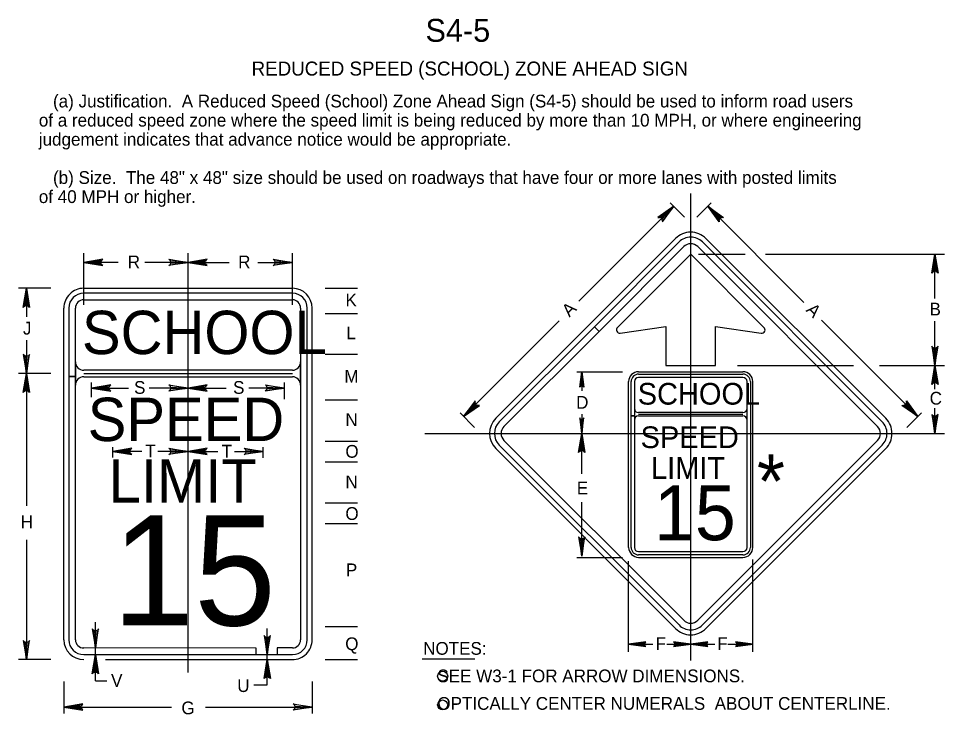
# Model space of a CAD drawing. Extents: x 0.012 to 0.205, y 0.005 to 0.259.
# Drawn here: x 0.023 to 0.2047, y 0.1227 to 0.2592 of the extents above; entities that cross this region are included whole.
import ezdxf

# ---------------------------------------------------------------- set-up
doc = ezdxf.new("R2010")
doc.units = 0
for name, color, linetype in [('1', 7, 'Continuous'), ('2', 7, 'Continuous'), ('3', 7, 'Continuous')]:
    doc.layers.add(name, color=color, linetype=linetype)

# ---------------------------------------------------------------- blocks, each defined once
blk = doc.blocks.new('RARROW')
at = {"layer": '3'}
for p, q in [((-2.156, 0.28500000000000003), (-2.2665, 0.384625)), ((-2.2665, 0.384625), (0, 0)), ((0, 0), (-2.2665, -0.379125)), ((-2.156, 0.28500000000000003), (-2.075625, 0.12075)), ((0, 0), (-2.156, 0.28500000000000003)), ((-2.14975, -0.2705), (0, 0)), ((-2.075625, 0.12075), (0, 0)), ((0, 0), (-2.074, -0.108)), ((-2.2665, -0.379125), (-2.14975, -0.2705)), ((-2.074, -0.108), (-2.14975, -0.2705))]:
    blk.add_line(p, q, dxfattribs=at)

msp = doc.modelspace()

# ---------------------------------------------------------------- linework, layer by layer
at = {"layer": '1'}
for p, q in [((0.15493652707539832, 0.13328541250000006), (0.15493652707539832, 0.22487989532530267)), ((0.1516063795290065, 0.22236153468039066), (0.13298510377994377, 0.203740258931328)), ((0.15373535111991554, 0.2202325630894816), (0.15091590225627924, 0.22305201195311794)), ((0.1561377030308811, 0.2202325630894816), (0.15895715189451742, 0.22305201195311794)), ((0.15826667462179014, 0.22236153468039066), (0.17713821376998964, 0.20348999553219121)), ((0.11667639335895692, 0.18077125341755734), (0.15195819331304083, 0.21605305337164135)), ((0.13602037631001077, 0.19874062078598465), (0.15264550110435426, 0.215365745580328)), ((0.15356191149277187, 0.21444933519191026), (0.1369367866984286, 0.19782421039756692)), ((0.1915929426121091, 0.17916753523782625), (0.15631114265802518, 0.21444933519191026)), ((0.157227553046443, 0.215365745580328), (0.19250935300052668, 0.18008394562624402)), ((0.1931966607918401, 0.18077125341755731), (0.15791486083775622, 0.21605305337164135)), ((0.03580431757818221, 0.20304977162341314), (0.03580431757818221, 0.21317677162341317)), ((0.056281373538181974, 0.20937914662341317), (0.056281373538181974, 0.21317677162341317)), ((0.05628137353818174, 0.13088051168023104), (0.056281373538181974, 0.21283153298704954)), ((0.0767584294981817, 0.20304977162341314), (0.0767584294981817, 0.21317677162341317)), ((0.15493652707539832, 0.2129793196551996), (0.14055945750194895, 0.19860225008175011)), ((0.16931359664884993, 0.19860225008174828), (0.15493652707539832, 0.2129793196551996)), ((0.15645266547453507, 0.2129793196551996), (0.16560148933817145, 0.21297931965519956)), ((0.16962927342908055, 0.21297931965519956), (0.20473300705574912, 0.2129793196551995)), ((0.20285847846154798, 0.20426678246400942), (0.20285847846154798, 0.2129793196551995)), ((0.042595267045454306, 0.21133549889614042), (0.03580431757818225, 0.21133549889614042)), ((0.05628137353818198, 0.21133549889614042), (0.047773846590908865, 0.21133549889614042)), ((0.05628137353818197, 0.21133549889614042), (0.06434530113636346, 0.21133549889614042)), ((0.06998419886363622, 0.21133549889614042), (0.0767584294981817, 0.21133549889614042)), ((0.029344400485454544, 0.20627697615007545), (0.02301502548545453, 0.20627697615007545)), ((0.024563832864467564, 0.20627697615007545), (0.024563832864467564, 0.20068718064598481)), ((0.03580431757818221, 0.20627697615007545), (0.0767584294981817, 0.20627697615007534)), ((0.08321834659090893, 0.20627697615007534), (0.08954772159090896, 0.20627697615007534)), ((0.0767584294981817, 0.2053049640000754), (0.03580431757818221, 0.20530496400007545)), ((0.03580431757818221, 0.20400894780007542), (0.0767584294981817, 0.2040089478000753)), ((0.03191626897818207, 0.13732891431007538), (0.03191626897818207, 0.20238892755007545)), ((0.03288828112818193, 0.20238892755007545), (0.03288828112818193, 0.18894456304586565)), ((0.034184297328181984, 0.18894456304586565), (0.034184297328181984, 0.20238892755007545)), ((0.07837844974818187, 0.20238892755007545), (0.07837844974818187, 0.13732891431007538)), ((0.07967446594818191, 0.13732891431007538), (0.07967446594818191, 0.20238892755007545)), ((0.08064647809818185, 0.13732891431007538), (0.08064647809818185, 0.20238892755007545)), ((0.08321834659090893, 0.20135211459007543), (0.08954772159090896, 0.20135211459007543)), ((0.18059060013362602, 0.20003760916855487), (0.1995051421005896, 0.18112306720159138)), ((0.12912993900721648, 0.1998850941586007), (0.11036791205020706, 0.18112306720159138)), ((0.11736370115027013, 0.18008394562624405), (0.13602037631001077, 0.19874062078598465)), ((0.13602037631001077, 0.19874062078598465), (0.1369367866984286, 0.19782421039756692)), ((0.1369367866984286, 0.19782421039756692), (0.13602037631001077, 0.19874062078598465)), ((0.14109770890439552, 0.19749001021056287), (0.15007652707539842, 0.19879471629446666)), ((0.15007652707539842, 0.19879471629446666), (0.15007652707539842, 0.19114171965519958)), ((0.1597965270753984, 0.19114171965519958), (0.1597965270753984, 0.19879471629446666)), ((0.1597965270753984, 0.19879471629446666), (0.16877534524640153, 0.19749001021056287)), ((0.20285847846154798, 0.19114171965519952), (0.20285847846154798, 0.1998362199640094)), ((0.1369367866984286, 0.19782421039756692), (0.11828011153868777, 0.1791675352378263)), ((0.024563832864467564, 0.19609190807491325), (0.024563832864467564, 0.18956005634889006)), ((0.08321834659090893, 0.19331681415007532), (0.08954772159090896, 0.19331681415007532)), ((0.034184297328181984, 0.19182639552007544), (0.034184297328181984, 0.18729033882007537)), ((0.07837844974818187, 0.18729033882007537), (0.07837844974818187, 0.19182639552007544)), ((0.15007652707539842, 0.19114171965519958), (0.1597965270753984, 0.19114171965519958)), ((0.1641054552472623, 0.19114171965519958), (0.1868912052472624, 0.19114171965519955)), ((0.1919547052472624, 0.19114171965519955), (0.20473300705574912, 0.19114171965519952)), ((0.20285847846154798, 0.18648699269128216), (0.20285847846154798, 0.19114171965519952)), ((0.029344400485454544, 0.18956005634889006), (0.02301502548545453, 0.18956005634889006)), ((0.024563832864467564, 0.18956005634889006), (0.024563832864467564, 0.1635639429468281)), ((0.0767584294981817, 0.19020637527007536), (0.03580431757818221, 0.19020637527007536)), ((0.03580431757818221, 0.1895583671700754), (0.0767584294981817, 0.18955836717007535)), ((0.13257365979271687, 0.18991051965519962), (0.14154986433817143, 0.18991051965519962)), ((0.13355183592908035, 0.18991051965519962), (0.13355183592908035, 0.18614175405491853)), ((0.14469812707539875, 0.18991051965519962), (0.1651749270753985, 0.1899105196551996)), ((0.14469812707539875, 0.18942451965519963), (0.1651749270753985, 0.1894245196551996)), ((0.03288828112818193, 0.18894456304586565), (0.034184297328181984, 0.18894456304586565)), ((0.03288828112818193, 0.18894456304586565), (0.034184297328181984, 0.18894456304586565)), ((0.034184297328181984, 0.18894456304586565), (0.03288828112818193, 0.18894456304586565)), ((0.03288828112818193, 0.18894456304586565), (0.034184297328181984, 0.18894456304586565)), ((0.034184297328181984, 0.18894456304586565), (0.03288828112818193, 0.18894456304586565)), ((0.034184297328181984, 0.18894456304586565), (0.03288828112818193, 0.18894456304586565)), ((0.03288828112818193, 0.18894456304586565), (0.03288828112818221, 0.13732891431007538)), ((0.034184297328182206, 0.13732891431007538), (0.034184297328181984, 0.18894456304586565)), ((0.03580431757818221, 0.18891035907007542), (0.0767584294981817, 0.18891035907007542)), ((0.0373595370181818, 0.18489913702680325), (0.0373595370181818, 0.1877889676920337)), ((0.056281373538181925, 0.18575254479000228), (0.056281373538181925, 0.18772194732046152)), ((0.0752032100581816, 0.1845052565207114), (0.0752032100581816, 0.1877889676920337)), ((0.1427541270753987, 0.15543691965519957), (0.1427541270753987, 0.1879665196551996)), ((0.14324012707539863, 0.18124442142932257), (0.14324012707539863, 0.1879665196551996)), ((0.14388812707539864, 0.1879665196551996), (0.14388812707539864, 0.18124442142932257)), ((0.1651749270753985, 0.18877651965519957), (0.14469812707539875, 0.1887765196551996)), ((0.16598492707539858, 0.15543691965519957), (0.16598492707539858, 0.1879665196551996)), ((0.16663292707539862, 0.1879665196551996), (0.16663292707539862, 0.15543691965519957)), ((0.16711892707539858, 0.1554369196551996), (0.16711892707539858, 0.1879665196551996)), ((0.0373595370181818, 0.18670442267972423), (0.04459689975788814, 0.18670442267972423)), ((0.05628137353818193, 0.18670442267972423), (0.04867994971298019, 0.18670442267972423)), ((0.05628137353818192, 0.18670442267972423), (0.06377870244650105, 0.18670442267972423)), ((0.0752032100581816, 0.18670442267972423), (0.0682012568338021, 0.18670442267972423)), ((0.08321834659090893, 0.18437430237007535), (0.08954772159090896, 0.18437430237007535)), ((0.11249688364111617, 0.17899409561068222), (0.10967743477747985, 0.18181354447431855)), ((0.14388812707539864, 0.1826853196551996), (0.14388812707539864, 0.18041731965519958)), ((0.1651749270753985, 0.18187531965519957), (0.14469812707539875, 0.18187531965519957)), ((0.16598492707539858, 0.18041731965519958), (0.16598492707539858, 0.1826853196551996)), ((0.19737617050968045, 0.17899409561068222), (0.20019561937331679, 0.18181354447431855)), ((0.20285847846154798, 0.1777929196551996), (0.20285847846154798, 0.18274690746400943)), ((0.13355183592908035, 0.18159611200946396), (0.13355183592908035, 0.17779291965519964)), ((0.14388812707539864, 0.18124442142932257), (0.14324012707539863, 0.18124442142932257)), ((0.14324012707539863, 0.15543691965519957), (0.14324012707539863, 0.18124442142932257)), ((0.14324012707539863, 0.18124442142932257), (0.14388812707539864, 0.18124442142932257)), ((0.14388812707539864, 0.18124442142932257), (0.14388812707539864, 0.15543691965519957)), ((0.14469812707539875, 0.1815513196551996), (0.1651749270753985, 0.18155131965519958)), ((0.14469812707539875, 0.18122731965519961), (0.1651749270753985, 0.1812273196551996)), ((0.08321834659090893, 0.17627420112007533), (0.08954772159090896, 0.17627420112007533)), ((0.10272620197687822, 0.17779291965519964), (0.20271464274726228, 0.1777929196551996)), ((0.11828011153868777, 0.176418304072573), (0.15356191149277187, 0.14113650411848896)), ((0.13257365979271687, 0.17779291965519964), (0.13510540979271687, 0.17779291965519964)), ((0.13355183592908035, 0.16985799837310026), (0.13355183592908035, 0.17779291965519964)), ((0.15631114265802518, 0.14113650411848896), (0.1915929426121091, 0.17641830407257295)), ((0.20020591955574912, 0.1777929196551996), (0.20473300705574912, 0.1777929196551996)), ((0.041506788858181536, 0.1730827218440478), (0.041506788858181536, 0.17511777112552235)), ((0.05628137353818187, 0.1733124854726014), (0.05628137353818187, 0.17528188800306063)), ((0.07105595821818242, 0.17301707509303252), (0.07105595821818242, 0.17511777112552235)), ((0.15195819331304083, 0.1395327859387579), (0.11667639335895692, 0.17481458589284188)), ((0.15264550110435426, 0.1402200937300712), (0.11736370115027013, 0.17550189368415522)), ((0.1925093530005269, 0.1755018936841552), (0.157227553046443, 0.1402200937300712)), ((0.15791486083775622, 0.1395327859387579), (0.1931966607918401, 0.17481458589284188)), ((0.04723572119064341, 0.17426436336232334), (0.041506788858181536, 0.17426436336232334)), ((0.05628137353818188, 0.17426436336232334), (0.0503867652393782, 0.17426436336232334)), ((0.05628137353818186, 0.17426436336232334), (0.06213753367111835, 0.17426436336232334)), ((0.06541987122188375, 0.17426436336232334), (0.07105595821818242, 0.17426436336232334)), ((0.08321834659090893, 0.17225655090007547), (0.08954772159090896, 0.17225655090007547)), ((0.08321834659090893, 0.16415644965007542), (0.08954772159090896, 0.16415644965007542)), ((0.13355183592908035, 0.15374086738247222), (0.13355183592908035, 0.16433418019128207)), ((0.08321834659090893, 0.16013879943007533), (0.08954772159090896, 0.16013879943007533)), ((0.024563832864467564, 0.156933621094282), (0.024563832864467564, 0.13344086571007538)), ((0.14469812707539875, 0.15462691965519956), (0.1651749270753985, 0.15462691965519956)), ((0.13257365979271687, 0.1534929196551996), (0.14154986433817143, 0.1534929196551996)), ((0.1427541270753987, 0.13497685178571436), (0.1427541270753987, 0.15271114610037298)), ((0.1651749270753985, 0.1539789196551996), (0.14469812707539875, 0.1539789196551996)), ((0.14469812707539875, 0.1534929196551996), (0.1651749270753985, 0.1534929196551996)), ((0.16711892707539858, 0.13497685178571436), (0.16711892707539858, 0.15305638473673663)), ((0.038107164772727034, 0.13570889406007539), (0.038107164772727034, 0.14077735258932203)), ((0.07182547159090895, 0.1344128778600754), (0.07182547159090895, 0.13951147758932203)), ((0.08321834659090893, 0.13992094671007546), (0.08954772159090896, 0.13992094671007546)), ((0.1427541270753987, 0.13645317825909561), (0.14750523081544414, 0.13645317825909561)), ((0.15026713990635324, 0.13645317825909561), (0.15493652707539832, 0.13645317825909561)), ((0.15493652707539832, 0.13645317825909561), (0.15964612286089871, 0.13645317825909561)), ((0.162235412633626, 0.1364531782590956), (0.16711892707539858, 0.1364531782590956)), ((0.06967049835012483, 0.1357051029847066), (0.0358043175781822, 0.13570889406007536)), ((0.038107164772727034, 0.1344128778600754), (0.038107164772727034, 0.13570889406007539)), ((0.06967049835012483, 0.1344128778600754), (0.06967049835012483, 0.1357051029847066)), ((0.0767584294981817, 0.13570889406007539), (0.07379924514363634, 0.13570889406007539)), ((0.07379924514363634, 0.13570889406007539), (0.07379924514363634, 0.1344128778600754)), ((0.029344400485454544, 0.13344086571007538), (0.02301502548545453, 0.13344086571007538)), ((0.0358043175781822, 0.13441287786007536), (0.06967049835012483, 0.1344128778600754)), ((0.038107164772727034, 0.12926939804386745), (0.038107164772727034, 0.1344128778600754)), ((0.040080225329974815, 0.13344086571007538), (0.07675842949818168, 0.13344086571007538)), ((0.06967049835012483, 0.1344128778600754), (0.07638853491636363, 0.1344128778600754)), ((0.07182547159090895, 0.13344086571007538), (0.07182547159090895, 0.1344128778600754)), ((0.07182547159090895, 0.12846384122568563), (0.07182547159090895, 0.13344086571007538)), ((0.07379924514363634, 0.1344128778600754), (0.0767584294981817, 0.1344128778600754)), ((0.08321834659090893, 0.13344086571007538), (0.08954772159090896, 0.13344086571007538)), ((0.10224769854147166, 0.13356283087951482), (0.112554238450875, 0.13356283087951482)), ((0.03191626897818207, 0.12916218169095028), (0.03191626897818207, 0.12283280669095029)), ((0.038107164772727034, 0.12926939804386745), (0.040318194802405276, 0.12926939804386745)), ((0.08064647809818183, 0.12916218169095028), (0.08064647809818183, 0.12283280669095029)), ((0.06920276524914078, 0.12846384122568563), (0.07182547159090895, 0.12846384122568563)), ((0.03191626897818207, 0.12412458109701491), (0.05300996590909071, 0.12412458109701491)), ((0.05968457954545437, 0.12412458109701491), (0.08064647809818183, 0.12412458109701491))]:
    msp.add_line(p, q, dxfattribs=at)
for centre in [(0.10625215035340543, 0.13017052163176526), (0.10625215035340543, 0.12452972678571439)]:
    msp.add_circle(centre, 0.0009847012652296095, dxfattribs=at)
for centre, radius, start, end in [((0.15493652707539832, 0.2130747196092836), 0.0042120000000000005, 44.999999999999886, 134.99999999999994), ((0.15493652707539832, 0.2130747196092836), 0.003239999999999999, 44.999999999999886, 134.99999999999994), ((0.15493652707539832, 0.21307471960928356), 0.0019440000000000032, 44.99999999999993, 134.99999999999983), ((0.03580431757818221, 0.20238892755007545), 0.0038880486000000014, 89.9999999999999, 180), ((0.0767584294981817, 0.20238892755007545), 0.0038880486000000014, 9.947598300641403e-14, 90), ((0.03580431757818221, 0.20238892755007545), 0.0029160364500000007, 90, 180), ((0.03580431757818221, 0.20238892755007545), 0.0016200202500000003, 90.00000000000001, 180), ((0.0767584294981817, 0.20238892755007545), 0.0029160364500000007, 1.4210854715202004e-13, 90), ((0.0767584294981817, 0.20238892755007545), 0.0016200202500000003, 0, 90), ((0.14100452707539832, 0.19813127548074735), 0.0006480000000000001, 133.38015095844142, 278.26774500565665), ((0.16886852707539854, 0.19813127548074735), 0.0006480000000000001, 261.73225499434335, 46.61984904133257), ((0.03580431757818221, 0.19182639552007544), 0.0016200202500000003, 180, 270), ((0.0767584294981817, 0.19182639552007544), 0.0016200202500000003, 270, 0), ((0.14469812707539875, 0.1879665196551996), 0.0019440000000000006, 89.9999999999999, 180), ((0.14469812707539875, 0.1879665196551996), 0.0014580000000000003, 90, 180), ((0.1651749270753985, 0.1879665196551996), 0.0019440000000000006, 9.947598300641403e-14, 90), ((0.1651749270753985, 0.1879665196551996), 0.0014580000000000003, 1.4210854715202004e-13, 90), ((0.03580431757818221, 0.18729033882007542), 0.0016200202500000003, 90, 180), ((0.0767584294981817, 0.18729033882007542), 0.0016200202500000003, 360, 90), ((0.14469812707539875, 0.1879665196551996), 0.0008100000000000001, 90.00000000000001, 180), ((0.1651749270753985, 0.1879665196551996), 0.0008100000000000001, 0, 90), ((0.14469812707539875, 0.1826853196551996), 0.0008100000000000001, 180, 270), ((0.1651749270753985, 0.1826853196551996), 0.0008100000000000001, 270, 0), ((0.1196547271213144, 0.17779291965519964), 0.0042120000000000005, 135.00000000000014, 225), ((0.1196547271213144, 0.17779291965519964), 0.0032400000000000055, 135, 225), ((0.14469812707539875, 0.1804173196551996), 0.0008100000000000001, 90, 180), ((0.1651749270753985, 0.1804173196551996), 0.0008100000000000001, 360, 90), ((0.19021832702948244, 0.17779291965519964), 0.003240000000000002, 315.0000000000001, 45.000000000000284), ((0.19021832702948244, 0.17779291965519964), 0.0042120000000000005, 315, 45.00000000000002), ((0.1196547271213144, 0.17779291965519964), 0.0019439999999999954, 134.99999999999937, 224.99999999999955), ((0.19021832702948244, 0.17779291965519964), 0.0019440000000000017, 314.9999999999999, 44.999999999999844), ((0.14469812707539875, 0.15543691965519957), 0.0019440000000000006, 180, 269.99999999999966), ((0.14469812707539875, 0.15543691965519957), 0.0014580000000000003, 180, 269.9999999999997), ((0.14469812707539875, 0.15543691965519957), 0.0008100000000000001, 180, 269.9999999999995), ((0.1651749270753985, 0.15543691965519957), 0.0019440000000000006, 270, 1.1368683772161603e-13), ((0.1651749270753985, 0.15543691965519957), 0.0014580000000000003, 270, 0), ((0.1651749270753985, 0.15543691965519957), 0.0008100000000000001, 270, 0), ((0.15493652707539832, 0.14251111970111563), 0.0032400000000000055, 224.99999999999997, 315), ((0.15493652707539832, 0.14251111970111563), 0.0019439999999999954, 225, 315), ((0.15493652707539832, 0.14251111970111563), 0.0042120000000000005, 224.99999999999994, 315), ((0.03580431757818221, 0.13732891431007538), 0.0038880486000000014, 180, 269.99999999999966), ((0.03580431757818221, 0.13732891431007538), 0.0029160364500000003, 180, 269.9999999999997), ((0.03580431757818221, 0.13732891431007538), 0.0016200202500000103, 180, 269.9999999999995), ((0.0767584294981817, 0.13732891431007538), 0.0038880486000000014, 270, 1.1368683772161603e-13), ((0.0767584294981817, 0.13732891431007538), 0.0016200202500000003, 270, 0), ((0.0767584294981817, 0.13732891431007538), 0.0029160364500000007, 270, 0)]:
    msp.add_arc(centre, radius, start, end, dxfattribs=at)

# ---------------------------------------------------------------- block references
at = {"layer": '3'}
for p, xscale, yscale, rotation in [((0.1516063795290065, 0.2223615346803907), 0.0016545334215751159, -0.0016366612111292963, 44.514681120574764), ((0.15826667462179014, 0.2223615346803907), 0.0016545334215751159, 0.0016366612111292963, 135.48531887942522), ((0.20285847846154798, 0.2129793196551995), 0.001654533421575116, 0.0016366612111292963, 89.99999999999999), ((0.03580431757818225, 0.21133549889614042), 0.001654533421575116, -0.0016366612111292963, 180), ((0.05628137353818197, 0.21133549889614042), 0.001654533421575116, -0.0016366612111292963, 180), ((0.024563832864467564, 0.20627697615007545), 0.001654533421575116, 0.0016366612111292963, 89.99999999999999), ((0.20285847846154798, 0.19114171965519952), 0.001654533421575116, -0.0016366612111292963, -89.99999999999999), ((0.024563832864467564, 0.18956005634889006), 0.001654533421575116, -0.0016366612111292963, -89.99999999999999), ((0.20285847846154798, 0.19114171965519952), 0.001654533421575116, 0.0016366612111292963, 89.99999999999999), ((0.024563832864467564, 0.18956005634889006), 0.001654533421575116, 0.0016366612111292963, 89.99999999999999), ((0.13355183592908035, 0.18991051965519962), 0.001340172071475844, 0.0010474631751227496, 90), ((0.0373595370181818, 0.18670442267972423), 0.001654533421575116, -0.0016366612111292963, 180), ((0.05628137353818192, 0.18670442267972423), 0.001654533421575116, -0.0016366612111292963, 180), ((0.11036791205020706, 0.18112306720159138), 0.0016545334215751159, -0.0016366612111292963, -135.48531887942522), ((0.1995051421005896, 0.18112306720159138), 0.0016545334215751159, 0.0016366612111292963, -44.51468112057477), ((0.13355183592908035, 0.17779291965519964), 0.001340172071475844, -0.0010474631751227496, -90), ((0.20285847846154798, 0.1777929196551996), 0.001654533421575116, -0.0016366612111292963, -89.99999999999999), ((0.13355183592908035, 0.17779291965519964), 0.001654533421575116, 0.0016366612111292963, 89.99999999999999), ((0.041506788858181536, 0.17426436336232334), 0.001654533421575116, -0.0016366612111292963, 180), ((0.05628137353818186, 0.17426436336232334), 0.001654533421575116, -0.0016366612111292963, 180), ((0.13355183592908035, 0.15374086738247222), 0.001654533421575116, -0.0016366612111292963, -89.99999999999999), ((0.038107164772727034, 0.13570889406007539), 0.001654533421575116, -0.0016366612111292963, -89.99999999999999), ((0.07182547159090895, 0.1344128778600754), 0.001654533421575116, -0.0016366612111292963, -89.99999999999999), ((0.024563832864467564, 0.13344086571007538), 0.001654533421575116, -0.0016366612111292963, -89.99999999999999), ((0.1427541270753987, 0.13645317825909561), 0.0014890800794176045, -0.0011456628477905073, 180), ((0.15493652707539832, 0.13645317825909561), 0.0014890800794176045, -0.0011456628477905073, 180), ((0.038107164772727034, 0.1344128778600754), 0.001654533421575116, 0.0016366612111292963, 89.99999999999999), ((0.07182547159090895, 0.13344086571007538), 0.001654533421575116, 0.0016366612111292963, 89.99999999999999), ((0.03191626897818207, 0.12412458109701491), 0.001654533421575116, -0.0016366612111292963, 180)]:
    msp.add_blockref('RARROW', p, dxfattribs=dict(at, xscale=xscale, yscale=yscale, rotation=rotation))
for p, xscale, yscale in [((0.05628137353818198, 0.21133549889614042), 0.001654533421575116, 0.0016366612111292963), ((0.0767584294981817, 0.21133549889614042), 0.001654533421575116, 0.0016366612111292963), ((0.05628137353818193, 0.18670442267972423), 0.001654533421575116, 0.0016366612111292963), ((0.0752032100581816, 0.18670442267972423), 0.001654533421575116, 0.0016366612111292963), ((0.05628137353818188, 0.17426436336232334), 0.001654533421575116, 0.0016366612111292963), ((0.07105595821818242, 0.17426436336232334), 0.001654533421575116, 0.0016366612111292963), ((0.15493652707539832, 0.13645317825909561), 0.0014890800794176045, -0.0011456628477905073), ((0.16711892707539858, 0.1364531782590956), 0.0014890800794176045, -0.0011456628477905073), ((0.08064647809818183, 0.12412458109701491), 0.001654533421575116, 0.0016366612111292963)]:
    msp.add_blockref('RARROW', p, dxfattribs=dict(at, xscale=xscale, yscale=yscale))

# ---------------------------------------------------------------- texts
at = {"layer": '1'}
for s, height, p in [('S4-5', 0.0045000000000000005, (0.10287409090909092, 0.254625)), ('REDUCED SPEED (SCHOOL) ZONE AHEAD SIGN', 0.00275025, (0.06876055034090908, 0.248)), ('SCHOOL', 0.008507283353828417, (0.035463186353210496, 0.19335799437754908)), ('SCHOOL', 0.00425358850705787, (0.14452756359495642, 0.18345110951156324)), ('SPEED', 0.008507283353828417, (0.03659421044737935, 0.17630378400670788)), ('SPEED', 0.00425358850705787, (0.14509306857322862, 0.1749241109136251)), ('*', 0.010584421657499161, (0.16792408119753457, 0.16312053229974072))]:
    msp.add_text(s, height=height, dxfattribs=at).set_placement(p)
for s, height, rotation, p in [('A', 0.0024997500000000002, 44.99999999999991, (0.13112956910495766, 0.20050376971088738)), ('A', 0.0024997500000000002, 315.0000000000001, (0.177391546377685, 0.20185570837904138)), ('LIMIT', 0.008507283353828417, 360, (0.040692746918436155, 0.16423986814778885)), ('LIMIT', 0.00425358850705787, 360, (0.14714231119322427, 0.16889222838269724)), ('15', 0.010796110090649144, 360, (0.14771652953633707, 0.156846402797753)), ('15', 0.021592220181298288, 360, (0.04140675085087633, 0.14012920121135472))]:
    msp.add_text(s, height=height, rotation=rotation, dxfattribs=at).set_placement(p)
at = {"layer": '2'}
for s, p in [('   (a) Justification.  A Reduced Speed (School) Zone Ahead Sign (S4-5) should be used to inform road users', (0.02699675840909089, 0.24174893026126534)), ('of a reduced speed zone where the speed limit is being reduced by more than 10 MPH, or where engineering', (0.02699675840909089, 0.23799918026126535)), ('judgement indicates that advance notice would be appropriate.', (0.02699675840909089, 0.23424943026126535)), ('   (b) Size.  The 48" x 48" size should be used on roadways that have four or more lanes with posted limits ', (0.02699675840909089, 0.22674993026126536)), ('of 40 MPH or higher.', (0.02699675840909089, 0.22300018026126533))]:
    msp.add_text(s, height=0.0024997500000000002, dxfattribs=at).set_placement(p)
at = {"layer": '3'}
for s, p in [('R', (0.04445344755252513, 0.21020060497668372)), ('B', (0.20180002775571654, 0.20094412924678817)), ('J', (0.023876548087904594, 0.19719958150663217)), ('L', (0.08734328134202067, 0.19627617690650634)), ('M', (0.08696074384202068, 0.18776009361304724)), ('S', (0.06511734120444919, 0.1855695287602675)), ('C', (0.20182426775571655, 0.18345473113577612)), ('D', (0.13244604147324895, 0.18264917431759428)), ('N', (0.08716148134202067, 0.17924440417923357)), ('T', (0.06287128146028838, 0.1730638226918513)), ('O', (0.08716148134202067, 0.1730299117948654)), ('N', (0.08716148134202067, 0.16704577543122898)), ('E', (0.13257974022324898, 0.16584756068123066)), ('O', (0.08716148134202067, 0.16083147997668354)), ('H', (0.023428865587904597, 0.1592015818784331)), ('P', (0.08725616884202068, 0.1497840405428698)), ('Q', (0.08713042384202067, 0.13528382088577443)), ('F', (0.14803259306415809, 0.13532572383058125)), ('V', (0.041180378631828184, 0.12807513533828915)), ('U', (0.06593885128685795, 0.12707342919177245)), ('G', (0.054982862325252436, 0.12270198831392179))]:
    msp.add_text(s, height=0.0024997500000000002, rotation=360, dxfattribs=at).set_placement(p)
for s, p in [('R', (0.06611707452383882, 0.21020060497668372)), ('K', (0.08718041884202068, 0.20272043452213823)), ('S', (0.04568610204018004, 0.1855695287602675)), ('T', (0.04789839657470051, 0.173096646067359)), ('NOTES:', (0.1024249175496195, 0.13437956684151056)), ('F', (0.16013532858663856, 0.13532572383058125)), ('   SEE W3-1 FOR ARROW DIMENSIONS.', (0.1024249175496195, 0.12898006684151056)), ('   OPTICALLY CENTER NUMERALS  ABOUT CENTERLINE.', (0.1024249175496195, 0.12358056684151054))]:
    msp.add_text(s, height=0.0024997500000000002, dxfattribs=at).set_placement(p)

doc.saveas('drawing.dxf')
